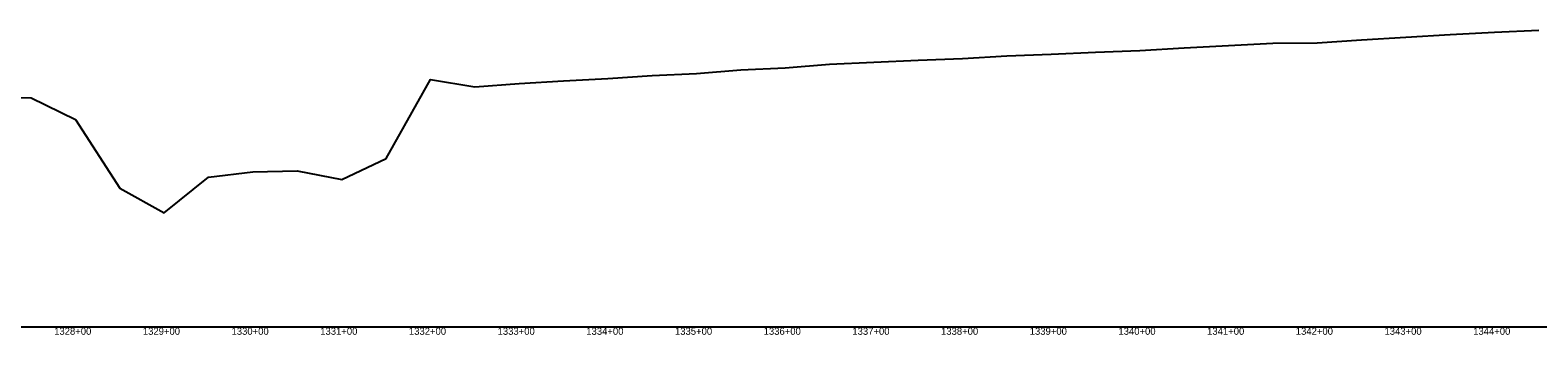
# Model space of a CAD drawing. Extents: x -3793 to 50787, y -1075 to 6138.
# Drawn here: x 18366 to 20066, y 4991 to 5335 of the extents above; entities that cross this region are included whole.
import ezdxf

# ---------------------------------------------------------------- set-up
doc = ezdxf.new("R2010")
doc.units = 0
for name, color, linetype in [('RD_DDB_Profile_EX', 7, 'Continuous'), ('RD_DDB_StaTX', 7, 'Continuous'), ('RD_GPK_Profile_Cell', 7, 'Continuous')]:
    doc.layers.add(name, color=color, linetype=linetype)

msp = doc.modelspace()

# ---------------------------------------------------------------- linework, layer by layer
at = {"layer": 'RD_DDB_Profile_EX'}
for points in [[(19216.8, 5292.377065), (19266.8, 5296.412865), (19316.8, 5298.90163), (19366.8, 5301.00029), (19416.8, 5302.84945), (19466.8, 5305.747215), (19516.8, 5307.750375), (19566.8, 5310.093065), (19616.8, 5312.101865), (19666.8, 5314.799905), (19716.8, 5317.442885), (19766.8, 5320.0267), (19816.8, 5320.71809), (19866.8, 5323.789295), (19916.8, 5326.80412), (19966.8, 5330.131385), (20016.8, 5332.634745), (20066.8, 5334.93842)], [(18316.8, 5260.02654), (18366.8, 5258.396435), (18416.8, 5234.170045), (18466.8, 5156.668585), (18516.8, 5128.82302), (18566.8, 5168.83773), (18616.8, 5175.04342), (18666.8, 5176.21682), (18716.8, 5166.143065), (18766.8, 5190.04429), (18816.8, 5279.055095), (18866.8, 5270.9754), (18916.8, 5274.67143), (18966.8, 5277.66309), (19016.8, 5280.377085), (19066.8, 5283.888425), (19116.8, 5286.08458), (19166.8, 5289.965505), (19216.8, 5292.377065)]]:
    msp.add_lwpolyline(points, dxfattribs=at)
at = {"layer": 'RD_GPK_Profile_Cell'}
msp.add_line((1000, 5000), (44802.949908, 5000), dxfattribs=at)

# ---------------------------------------------------------------- texts
at = {"layer": 'RD_DDB_StaTX'}
for s, p in [('1328+00', (18392.595471, 4991)), ('1328+00', (18392.595471, 4991)), ('1329+00', (18492.595471, 4991)), ('1329+00', (18492.595471, 4991)), ('1330+00', (18592.595471, 4991)), ('1330+00', (18592.595471, 4991)), ('1331+00', (18692.595471, 4991)), ('1331+00', (18692.595471, 4991)), ('1332+00', (18792.595471, 4991)), ('1332+00', (18792.595471, 4991)), ('1333+00', (18892.595471, 4991)), ('1333+00', (18892.595471, 4991)), ('1334+00', (18992.595471, 4991)), ('1334+00', (18992.595471, 4991)), ('1335+00', (19092.595471, 4991)), ('1335+00', (19092.595471, 4991)), ('1336+00', (19192.595471, 4991)), ('1336+00', (19192.595471, 4991)), ('1337+00', (19292.595471, 4991)), ('1337+00', (19292.595471, 4991)), ('1338+00', (19392.595471, 4991)), ('1338+00', (19392.595471, 4991)), ('1339+00', (19492.595471, 4991)), ('1339+00', (19492.595471, 4991)), ('1340+00', (19592.595471, 4991)), ('1340+00', (19592.595471, 4991)), ('1341+00', (19692.595471, 4991)), ('1341+00', (19692.595471, 4991)), ('1342+00', (19792.595471, 4991)), ('1342+00', (19792.595471, 4991)), ('1343+00', (19892.595471, 4991)), ('1343+00', (19892.595471, 4991)), ('1344+00', (19992.595471, 4991)), ('1344+00', (19992.595471, 4991))]:
    msp.add_text(s, height=8, dxfattribs=at).set_placement(p)

doc.saveas('drawing.dxf')
